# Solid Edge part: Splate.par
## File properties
Title: Side Plate
Subject: Carrier Assembly
Author: edge
Keywords: Side Plate
Comments: Side Plate
Template: metric.par
Last saved by: edge
Revision: 34
Application: Solid Edge
File Size: 0
Number of Sheets: 0
Number of Objects: 0
Username: edge
文書内容のタイプ: 0
Material: Steel
Face Style: Steel
Fill Style: ANSI32(Steel)
Virtual Style: Machined steel
Coef. of Thermal Exp: 1.3e-05
Thermal Conductivity: 32.0
Specific Heat: 481.0
Modulus of Elasticity: 199947953000.0
Poisson's Ratio: 0.29
Yield Stress: 262000766.0
Ultimate Stress: 358527364.0
Elongation: 0.0
Category: Machined Plate
Manager: Brian Little
Company: Wheels R Us
Density: 0.28298507824 lbm/in^3
Accuracy: 0.00
Document Number: SP-2070
Revision: 1
Project Name: Trolley Wheel Assembly
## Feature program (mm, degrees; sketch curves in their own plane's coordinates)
sketch for "unnamed Protrusion 1" plane through (0, 0, 0) normal (0, -1, 0) x-axis (1, 0, 0)
  line (-41.3956, 47.354) -> (78.6044, 47.354)
  line (78.6044, 47.354) -> (78.6044, -2.646)
  line (78.6044, -2.646) -> (43.6044, -132.646)
  line (43.6044, -132.646) -> (-6.3956, -132.646)
  line (-41.3956, -2.646) -> (-6.3956, -132.646)
  line (-41.3956, 47.354) -> (-41.3956, -2.646)
extrude "unnamed Protrusion 1" add finite 15 along -normal
sketch for "unnamed Hole 1" plane through (18.6044, 0, -42.646) normal (0, -1, 0) x-axis (1, 0, 0)
  hole centre (0, -60) bore radius 15
hole "unnamed Hole 1" through
sketch for "Hole_2" plane through (18.6044, 0, -42.646) normal (0, -1, 0) x-axis (1, 0, 0)
  hole centre (30, 65) bore radius 10
hole "Hole_2" through
sketch for "Hole_3" plane through (18.6044, 0, -42.646) normal (0, -1, 0) x-axis (1, 0, 0)
  hole centre (-30, 65) bore radius 10
hole "Hole_3" through
pattern "unnamed Pattern 1" of "Hole_2", "Hole_3"
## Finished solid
Body 1: solid body, 11 faces, 24 edges, 12 vertices.
  Faces by surface: plane 8, cylinder 3
  Edges by curve: line 18, circle 6
Bounding box of the edges (mm): 120.000 x 15.000 x 180.000, from (-41.3956, 0, -132.646) to (78.6044, 15, 47.354).
Cylindrical faces by radius (mm): R10 x2, R15 x1
Planar faces by outward normal: +x 1, +y 1, +z 1, -x 1, -y 1, -z 1, oblique 2
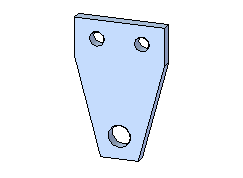
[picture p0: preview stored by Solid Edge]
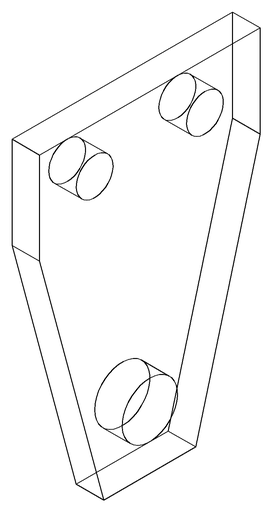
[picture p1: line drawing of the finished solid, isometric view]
